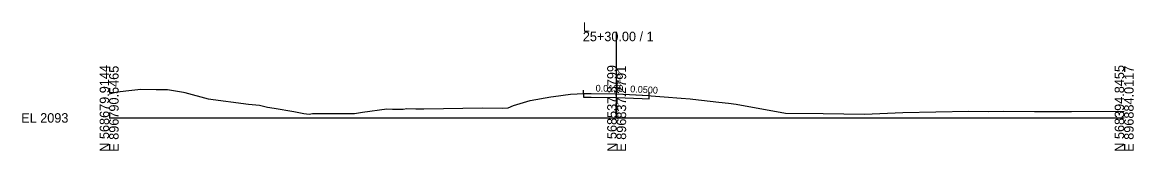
# Model space of a CAD drawing. Extents: x -26 to 1603, y -10 to 13527.
# Drawn here: x -25.7 to 302.8, y 12990.3 to 13028.2 of the extents above; entities that cross this region are included whole.
import ezdxf

# ---------------------------------------------------------------- set-up
doc = ezdxf.new("R2010")
doc.units = 0
for name, color, linetype in [('Default', 7, 'Continuous'), ('Exist XS Center Line Elevation Label', 7, 'Continuous'), ('Exist XS Ground Line', 7, 'Continuous'), ('Old_Level_61', 7, 'Continuous'), ('Old_Level_63', 7, 'Continuous'), ('Prop XS EOT Tick Mark', 7, 'Continuous'), ('Prop XS Finish Grade Pavement', 7, 'Continuous'), ('Prop XS Subgrade Earthwork', 7, 'Continuous'), ('Prop XSC Text', 7, 'Continuous')]:
    doc.layers.add(name, color=color, linetype=linetype)

msp = doc.modelspace()

# ---------------------------------------------------------------- linework, layer by layer
at = {"layer": 'Exist XS Ground Line'}
for p, q in [((0, 13007.08), (2.4, 13007.73)), ((2.4, 13007.73), (6.7, 13008.21)), ((6.7, 13008.21), (9.37, 13008.48)), ((9.37, 13008.48), (13.89, 13008.41)), ((13.89, 13008.41), (17.28, 13008.36)), ((17.28, 13008.36), (21.94, 13007.62)), ((21.94, 13007.62), (22.4, 13007.47)), ((22.4, 13007.47), (29.22, 13005.63)), ((131.3, 13006.29), (136.32, 13006.99)), ((136.32, 13006.99), (140.28, 13007.16)), ((140.28, 13007.16), (142.51, 13007.16)), ((142.51, 13007.16), (149.96, 13007.06)), ((149.96, 13007.06), (157.53, 13006.69)), ((157.53, 13006.69), (159.68, 13006.6)), ((29.22, 13005.63), (41.17, 13004.1)), ((41.17, 13004.1), (44.39, 13003.78)), ((44.39, 13003.78), (46.77, 13003.22)), ((117.9, 13002.98), (119.48, 13003.65)), ((119.48, 13003.65), (124.45, 13005.17)), ((124.45, 13005.17), (130.58, 13006.18)), ((130.58, 13006.18), (131.3, 13006.29)), ((159.68, 13006.6), (160.24, 13006.55)), ((160.24, 13006.55), (164.01, 13006.23)), ((164.01, 13006.23), (169.08, 13005.84)), ((169.08, 13005.84), (171.76, 13005.59)), ((171.76, 13005.59), (172.47, 13005.49)), ((172.47, 13005.49), (180.19, 13004.63)), ((180.19, 13004.63), (183.02, 13004.34)), ((183.02, 13004.34), (185.35, 13004.01)), ((185.35, 13004.01), (199.86, 13001.43)), ((46.77, 13003.22), (48.75, 13002.83)), ((48.75, 13002.83), (54.61, 13001.89)), ((54.61, 13001.89), (57.58, 13001.31)), ((57.58, 13001.31), (59.15, 13001.12)), ((59.15, 13001.12), (60.08, 13001.33)), ((60.08, 13001.33), (72.47, 13001.27)), ((72.47, 13001.27), (74.83, 13001.71)), ((74.83, 13001.71), (82.12, 13002.67)), ((82.12, 13002.67), (83.75, 13002.61)), ((83.75, 13002.61), (86.91, 13002.63)), ((86.91, 13002.63), (87.99, 13002.78)), ((87.99, 13002.78), (90.6, 13002.64)), ((90.6, 13002.64), (93, 13002.64)), ((93, 13002.64), (110.39, 13002.96)), ((110.39, 13002.96), (116.17, 13002.84)), ((116.17, 13002.84), (117.9, 13002.98)), ((199.86, 13001.43), (210.99, 13001.26)), ((210.99, 13001.26), (223.29, 13001.13)), ((223.29, 13001.13), (234.58, 13001.57)), ((234.58, 13001.57), (254.1, 13001.98)), ((254.1, 13001.98), (259.97, 13001.92)), ((259.97, 13001.92), (264.19, 13002)), ((264.19, 13002), (273.49, 13001.85)), ((273.49, 13001.85), (284.41, 13001.86)), ((284.41, 13001.86), (300, 13002))]:
    msp.add_line(p, q, dxfattribs=at)
at = {"layer": 'Old_Level_61'}
for p, q in [((140.24, 13007.16), (140.24, 13006.16)), ((140.24, 13006.16), (140.28, 13006.16)), ((140.28, 13006.16), (141.24, 13006.16)), ((141.24, 13006.16), (142.51, 13006.16)), ((142.51, 13006.16), (149.96, 13006.06)), ((149.96, 13006.06), (157.53, 13005.69)), ((157.53, 13005.69), (159.65, 13005.6)), ((159.65, 13005.6), (159.65, 13006.6))]:
    msp.add_line(p, q, dxfattribs=at)
at = {"layer": 'Old_Level_63'}
for p, q in [((150, 13000), (150, 13025.44)), ((0, 13000), (150, 13000)), ((150, 13000), (300, 13000))]:
    msp.add_line(p, q, dxfattribs=at)
at = {"layer": 'Prop XS EOT Tick Mark'}
for p, q in [((140.24, 13007.16), (140.24, 13008.16)), ((159.65, 13006.6), (159.65, 13007.6))]:
    msp.add_line(p, q, dxfattribs=at)
at = {"layer": 'Prop XS Finish Grade Pavement'}
for p, q in [((140.24, 13007.16), (150, 13007.06)), ((150, 13007.06), (159.65, 13006.6))]:
    msp.add_line(p, q, dxfattribs=at)
at = {"layer": 'Prop XS Subgrade Earthwork'}
for p, q in [((140.01, 13007.19), (139.98, 13007.14)), ((140.08, 13007.11), (140.01, 13007.19)), ((140.12, 13007.15), (140.08, 13007.11))]:
    msp.add_line(p, q, dxfattribs=at)

# ---------------------------------------------------------------- texts
at = {"layer": 'Default'}
for s, rotation, p in [('0.0130', 359.1406, (143.78, 13007.77)), ('0.0500', 357.1376, (153.97, 13007.56))]:
    msp.add_text(s, height=2, rotation=rotation, dxfattribs=at).set_placement(p)
at = {"layer": 'Exist XS Center Line Elevation Label'}
msp.add_text('2100.05', height=1, rotation=90, dxfattribs=at).set_placement((150.5, 12999.45))
at = {"layer": 'Old_Level_63'}
for s, p in [('L', (140, 13025.44)), ('25+30.00 / 1', (140, 13022.64)), ('EL 2093', (-26, 12998.6))]:
    msp.add_text(s, height=2.8, dxfattribs=at).set_placement(p)
for s, p in [('N 568679.9144', (0, 12990)), ('E 896790.5465', (2.8, 12990)), ('N 568537.3799', (150, 12990)), ('E 896837.2791', (152.8, 12990)), ('N 568394.8455', (300, 12990)), ('E 896884.0117', (302.8, 12990))]:
    msp.add_text(s, height=2.8, rotation=90, dxfattribs=at).set_placement(p)
at = {"layer": 'Prop XSC Text'}
msp.add_text(' 2100.06', height=1.2, rotation=90, dxfattribs=at).set_placement((151.2, 13007.06))

doc.saveas('drawing.dxf')
